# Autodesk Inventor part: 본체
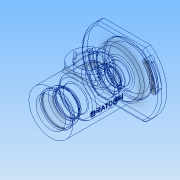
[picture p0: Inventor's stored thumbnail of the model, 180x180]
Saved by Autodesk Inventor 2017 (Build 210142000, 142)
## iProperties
Part Number: 본체
Material: 알루미늄 6061
Document SubType Name: Modeling
Designer: MRC
Density: 2.7 g/cm^3
Appearance: 알루미늄 - 평지
Mass: 706.457 g
Surface Area: 619.341 cm^2
Volume: 261.651 cm^3
Author: MRC
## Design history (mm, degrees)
sketch "스케치1"
  geometry: C1 r 32 at (0, 0); 1 further point
  constraints: 1 centre point, 1 coincident
  dimensions: "d0" = 64 diameter of C1
extrude "돌출1" new body sketch "스케치1" stored distance "d1" = 102; taper "d2" = 0 deg
sketch "스케치2"
  geometry: C1 r 58 at (0, 0); 1 further point
  constraints: 1 centre point, 1 coincident
  dimensions: "d3" = 116 diameter of C1
extrude "돌출2" join sketch "스케치2" distance "d4" = 10; taper "d5" = 0 deg
sketch "스케치3"
  geometry: C1 r 36 at (0, 0); 1 further point
  constraints: 1 centre point, 1 coincident
  dimensions: "d6" = 72 diameter of C1
extrude "돌출3" join sketch "스케치3" distance "d7" = 3; taper "d8" = 0 deg
sketch "스케치4"
  geometry: L1 (-47, -33.985)-(-47, 33.985); L2 (47, -33.985)-(47, 33.985); A1 r 58 centre (0, 0) between (-47, -33.985) and (-47, 33.985) reference; 1 further point
  constraints: 4 end point, 4 point on circle, 2 vertical
  dimensions: "d9" = 94 distance between parallel lines of L2 L1; "d10" = 47 distance from line of point (0, 0) L1
extrude "돌출4" cut sketch "스케치4" distance "d11" = 31.25; taper "d12" = 0 deg
node "작업 평면1"
sketch "스케치5"
  geometry: L1 (32, 51)-(-32, 51) reference; C1 r 25 at (0, -5); 1 further point
  constraints: 1 centre point, 1 vertical alignment
  dimensions: "d14" = 50 diameter of C1; "d15" = 56 distance from line of L1 C1.centre
extrude "돌출5" join sketch "스케치5" stored distance "d16" = 31.25; taper "d17" = 5 deg
sketch "스케치7"
  geometry: 2 further points
  constraints: 1 coincident
hole "구멍1" sketch "스케치7" at (0, 0) diameter "d20" = 43.376; stored, may be unused: countersink angle "d24" = 90 deg, drill point angle "d26" = 0 deg; dims "d21" = 90, "d22" = 4, "d23" = 2, "d25" = 8
sketch "스케치8"
  geometry: L1 (32, 51)-(-32, 51) reference; L2 (-36, -64)-(36, -64) reference; L3 (21.688, 43)-(-21.688, 43) reference; L4 (0, 43)-(0, -64); L5 (0, 43)-(-24, 43); L6 (-24, 43)-(-24, 40); L7 (-24, 40)-(-22.5, 40); L8 (-22.5, 40)-(-22.5, 29); L9 (-22.5, 29)-(-17.5, 29); L10 (-17.5, 29)-(-17.5, 26.75); L11 (-17.5, 26.75)-(-18.5, 26.75); L12 (-18.5, 26.75)-(-18.5, 25); L13 (-18.5, 25)-(-17.5, 25); L14 (-17.5, 25)-(-17.5, 14); L15 (-17.5, 14)-(-27, 14); L16 (-27, 14)-(-27, -24); L17 (-27, -24)-(-17.5, -24); L18 (-17.5, -24)-(-17.5, -35); L19 (-17.5, -35)-(-15, -35); L20 (-15, -35)-(-15, -40); L21 (-15, -40)-(-11, -40); L22 (-11, -40)-(-11, -42.7); L23 (-11, -42.7)-(-15, -42.7); L24 (-15, -42.7)-(-15, -50); L25 (-30, -64)-(0, -64); L26 (-15, -50)-(-20, -50); L27 (-32, -51)-(32, -51) reference; L28 (-20, -50)-(-30, -64); 1 further point
  constraints: 48 end point, 18 perpendicular, 4 point on line, 2 midpoint, 1 horizontal, 1 parallel
  dimensions: "d27" = 48 diameter of L6 L4; "d28" = 45 diameter of L8 L4; "d29" = 35 diameter of L10 L4; "d30" = 37 diameter of L12 L4; "d31" = 54 diameter of L16 L4; "d32" = 35 diameter of L18 L4; "d33" = 30 diameter of L20 L4; "d34" = 22 diameter of L22 L4; "d35" = 30 diameter of L24 L4; "d36" = 60 diameter of L25.start L4; "d37" = 3 distance of L5.end L6.end; "d38" = 22 distance between parallel lines of L9 L1; "d40" = 4 distance between parallel lines of L13 L9; "d41" = 1.75 distance of L11.end L12.end; "d42" = 11 distance between parallel lines of L15 L13; "d43" = 38 distance of L15.end L16.end; "d44" = 11 distance of L17.end L18.end; "d45" = 5 distance of L19.end L20.end; "d46" = 14 distance from line of L2 L24.end; "d47" = 7.3 distance of L23.end L24.end; "d107" = 40 diameter of L26.end L4
revolve "회전1" sketch "스케치8" stored, may be unused: angle "d48" = 90 deg
sketch "스케치9"
  geometry: C1 r 25 at (0, 0) reference; C2 r 16 at (0, 0); 1 further point
  constraints: 1 centre point, 1 coincident
  dimensions: "d49" = 32 diameter of C2
extrude "돌출6" cut sketch "스케치9" distance "d50" = 39; taper "d51" = 0 deg
sketch "스케치10"
  geometry: C1 r 16 at (0, 0) reference; A1 r 20.5 centre (0, 0) between (0, 20.5) and (0, -20.5); 1 further point
  constraints: 2 point on circle, 2 vertical alignment, 1 centre point, 1 coincident
  dimensions: "d52" = 41 diameter of A1
hole "구멍2" sketch "스케치10" at (0, 20.5), (0, -20.5) diameter "d53" = 2.459; stored, may be unused: countersink angle "d57" = 90 deg, drill point angle "d59" = 118 deg; dims "d54" = 6, "d55" = 4, "d56" = 2, "d58" = 8
sketch "스케치13"
  geometry: L1 (0, 0)-(30.854, -36.77); L2 (0, 0)-(0, -48); L3 (0, 0)-(-30.854, 36.77); A1 r 48 centre (0, 0) between (30.854, -36.77) and (0, -48); 3 further points
  constraints: 6 end point, 3 coincident, 3 point on circle, 1 centre point, 1 vertical
  dimensions: "d71" = 96 diameter of A1; "d72" = 40 deg angle of L2 L1; "d73" = 40 deg angle of L3 L2
hole "구멍4" sketch "스케치13" at (-30.854, 36.77), (30.854, -36.77) diameter "d74" = 8; stored, may be unused: countersink angle "d78" = 90 deg, drill point angle "d80" = 118 deg; dims "d75" = 6, "d76" = 8, "d77" = 4.4, "d79" = 8
sketch "스케치14"
  geometry: L1 (-47, -33.985)-(-47, 33.985) reference; L2 (47, 33.985)-(47, -33.985) reference; C1 r 32 at (0, 0) reference; C2 r 20.714 at (0, 0) reference; A1 r 4 centre (-30.854, 36.77) between (-28.283, 33.706) and (-33.425, 39.834) reference; A2 r 4 centre (30.854, -36.77) between (28.283, -33.706) and (33.425, -39.834) reference; A3 r 58 centre (0, 0) between (47, 33.985) and (-47, 33.985) reference; A4 r 58 centre (0, 0) between (-47, -33.985) and (47, -33.985) reference; A5 r 48 centre (0, 0) between (30.854, -36.77) and (0, 48); A6 r 44 centre (0, 0) between (0, 44) and (-28.283, 33.706); A7 r 52 centre (0, 0) between (47, 22.249) and (0, 52); A8 r 4 centre (0, 48) between (0, 52) and (0, 44); A9 r 4 centre (0, -48) between (0, -44) and (0, -52); A10 r 52 centre (0, 0) between (47, -22.249) and (47, 22.249); A11 r 52 centre (0, 0) between (0, 52) and (-33.425, 39.834); A12 r 44 centre (0, 0) between (28.283, -33.706) and (0, 44); A13 r 44 centre (0, 0) between (0, -44) and (28.283, -33.706); A14 r 44 centre (0, 0) between (-28.283, 33.706) and (0, -44); A15 r 52 centre (0, 0) between (-47, 22.249) and (-47, -22.249); A16 r 52 centre (0, 0) between (-47, -22.249) and (0, -52); A17 r 52 centre (0, 0) between (0, -52) and (33.425, -39.834); A18 r 52 centre (0, 0) between (-33.425, 39.834) and (-47, 22.249); A19 r 52 centre (0, 0) between (33.425, -39.834) and (47, -22.249); 1 further point
  constraints: 35 point on circle, 15 centre point, 4 point on line, 4 tangent, 3 coincident, 2 vertical alignment
extrude "돌출7" cut sketch "스케치14" distance "d81" = 4.4; taper "d82" = 0 deg
sketch "스케치15"
  geometry: L1 (-47, -33.985)-(-47, 33.985) reference; L2 (47, 33.985)-(47, -33.985) reference; C1 r 23.857 at (0, 0) reference; A1 r 44 centre (0, 0) between (0, 44) and (-28.283, 33.706) reference; A2 r 4 centre (0, 48) between (0, 44) and (0, 52) reference; A3 r 52 centre (0, 0) between (0, 52) and (-33.425, 39.834) reference; A4 r 4 centre (-30.854, 36.77) between (-28.283, 33.706) and (-33.425, 39.834) reference; A5 r 4 centre (-30.854, 36.77) between (-33.425, 39.834) and (-28.283, 33.706) reference; A6 r 4 centre (0, -48) between (0, -44) and (0, -52) reference; A7 r 52 centre (0, 0) between (0, -52) and (33.425, -39.834) reference; A8 r 4 centre (30.854, -36.77) between (33.425, -39.834) and (28.283, -33.706) reference; A9 r 44 centre (0, 0) between (0, -44) and (28.283, -33.706) reference; A10 r 4 centre (30.854, -36.77) between (28.283, -33.706) and (33.425, -39.834) reference; A11 r 58 centre (0, 0) between (47, 33.985) and (-47, 33.985) reference; A12 r 58 centre (0, 0) between (-47, -33.985) and (47, -33.985) reference; A13 r 2.25 centre (0, 48) between (0, 50.25) and (0, 45.75); A14 r 2.25 centre (0, -48) between (0, -45.75) and (0, -50.25); A15 r 45.75 centre (0, 0) between (3.227, 45.636) and (0, 45.75); A16 r 50.25 centre (0, 0) between (3.382, 50.136) and (0, 50.25); A17 r 50.25 centre (0, 0) between (47, 17.778) and (3.382, 50.136); A18 r 50.25 centre (0, 0) between (47, -17.778) and (47, 17.778); A19 r 50.25 centre (0, 0) between (34.818, -36.233) and (47, -17.778); A20 r 45.75 centre (0, 0) between (31.806, -32.885) and (3.227, 45.636); A21 r 45.75 centre (0, 0) between (-26.862, 37.033) and (0, -45.75); A22 r 50.25 centre (0, 0) between (-29.636, 40.58) and (0, -50.25); A23 r 45.75 centre (0, 0) between (0, -45.75) and (26.862, -37.033); A24 r 50.25 centre (0, 0) between (0, -50.25) and (29.636, -40.58); A25 r 45.75 centre (0, 0) between (26.862, -37.033) and (31.806, -32.885); A26 r 50.25 centre (0, 0) between (29.636, -40.58) and (34.818, -36.233); A27 r 50.25 centre (0, 0) between (0, 50.25) and (-29.636, 40.58); A28 r 45.75 centre (0, 0) between (0, 45.75) and (-26.862, 37.033); 1 further point
  constraints: 40 point on circle, 16 centre point, 4 coincident, 2 point on line, 2 tangent
  dimensions: "d83" = 4.5 diameter of A13; "d84" = 4.5 diameter of A14
extrude "돌출8" cut sketch "스케치15" stored distance "d85" = 4.4; taper "d86" = 0 deg
fillet "모깎기1" dims "d87" = 0.6
fillet "모깎기2" dims "d88" = 0.5
chamfer "모따기1" distance "d89" = 0.7; stored, may be unused: second distance "d90" = 2, angle "d91" = 30 deg
chamfer "모따기2" distance "d92" = 1; stored, may be unused: second distance "d93" = 2, angle "d94" = 30 deg
fillet "모깎기3" dims "d95" = 3
fillet "모깎기4" dims "d96" = 3
fillet "모깎기5" dims "d97" = 3
chamfer "모따기3" distance "d98" = 1; stored, may be unused: second distance "d99" = 2, angle "d100" = 30 deg
fillet "모깎기6" dims "d101" = 3
node "작업 평면3"
sketch "스케치16"
  geometry: L1 (-47, -61)-(47, -61) reference; 2 further points
  constraints: 1 other
  dimensions: "d103" = 62 distance from line of L1 point (0, 1); "d104" = 0 horizontal distance of point (0, 0) point (0, 1)
feature "엠보싱1" sketch "스케치16" dims "d9" = 94, "d105" = 0.5, "d106" = 0
fillet "모깎기7" dims "d108" = 3
chamfer "모따기4" distance "d109" = 1; stored, may be unused: second distance "d110" = 2, angle "d111" = 30 deg
chamfer "모따기5" distance "d112" = 1; stored, may be unused: second distance "d113" = 2, angle "d114" = 30 deg
node "솔리드1"
node "절단 모서리 투영1"
node "절단 모서리 투영2"
other parameters: "d13" = 38, "d102" = -78.25
